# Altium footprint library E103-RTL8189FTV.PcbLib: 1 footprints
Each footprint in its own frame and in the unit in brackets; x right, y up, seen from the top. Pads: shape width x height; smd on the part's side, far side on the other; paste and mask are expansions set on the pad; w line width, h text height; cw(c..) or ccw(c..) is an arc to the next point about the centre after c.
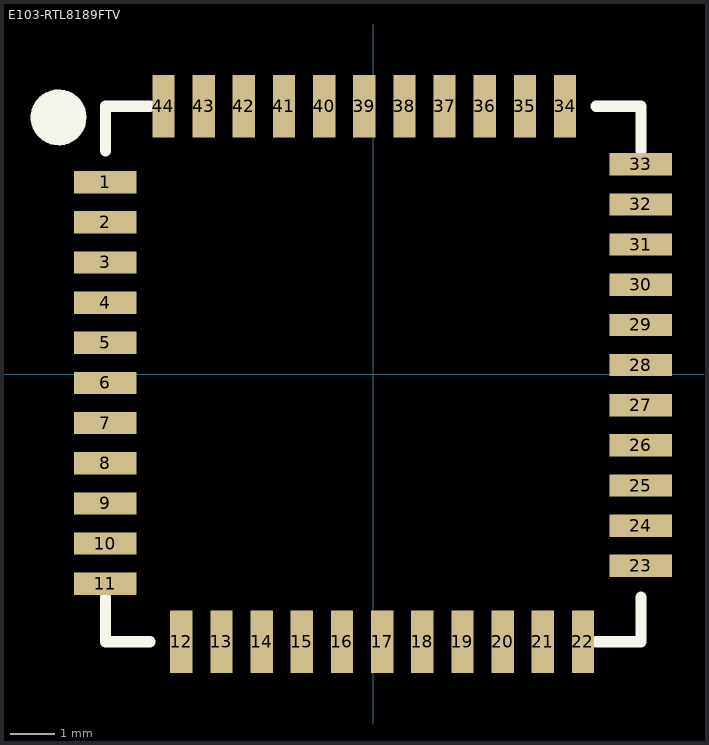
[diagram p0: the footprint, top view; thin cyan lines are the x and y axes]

## E103-RTL8189FTV [mm]
pads (44):
  rect 1.4x0.5 smd mask+0: 1(-6,4.3) 2(-6,3.4) 3(-6,2.5) 4(-6,1.6) 5(-6,0.7) 6(-6,-0.2) 7(-6,-1.1) 8(-6,-2) 9(-6,-2.9) 10(-6,-3.8) 11(-6,-4.7) 23(6,-4.3) 24(6,-3.4) 25(6,-2.5) 26(6,-1.6) 27(6,-0.7) 28(6,0.2) 29(6,1.1) 30(6,2) 31(6,2.9) 32(6,3.8) 33(6,4.7)
  rect 0.5x1.4 smd mask+0: 12(-4.3,-6) 13(-3.4,-6) 14(-2.5,-6) 15(-1.6,-6) 16(-0.7,-6) 17(0.2,-6) 18(1.1,-6) 19(2,-6) 20(2.9,-6) 21(3.8,-6) 22(4.7,-6) 34(4.3,6) 35(3.4,6) 36(2.5,6) 37(1.6,6) 38(0.7,6) 39(-0.2,6) 40(-1.1,6) 41(-2,6) 42(-2.9,6) 43(-3.8,6) 44(-4.7,6)
Top Overlay:
  circle w0.254: c-7.05,5.75 r0.5
  region: -6.855,6.221 -6.69,6.11 -6.579,5.945 -6.54,5.75 -6.579,5.555 -6.69,5.39 -6.855,5.279 -7.05,5.24 -7.245,5.279 -7.41,5.39 -7.521,5.555 -7.56,5.75 -7.521,5.945 -7.41,6.11 -7.245,6.221 -7.05,6.26
  lines w0.254: -6,-5 -6,-6 -5,-6 ; -6,5 -6,6 -5,6 ; 5,-6 6,-6 6,-5 ; 5,6 6,6 6,5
